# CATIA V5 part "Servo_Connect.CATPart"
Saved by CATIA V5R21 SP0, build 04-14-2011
Part number: Servo_Connect
Bounding box of the stored display mesh (mm): x 0 to 5, y -12.25 to 12.25, z -12.161 to 12.161
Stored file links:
  F:\教程\Robotic_Arm_Arduino_Kinect\机械臂CAD\Arm_Detailed_Design\Servo_Connect.CATPart
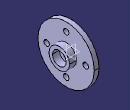
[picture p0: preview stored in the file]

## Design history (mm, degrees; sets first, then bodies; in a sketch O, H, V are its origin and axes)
Body1 (main body)
  Sketch1 on yz-plane, origin (0, 0, 0), H (0, 1, 0), V (0, 0, 1)
    circle A1 centre (0, 0) radius 12.25
    circle A2 centre (0, 8.5) radius 1.25
    point P1 (0, 8.5)
    circle A3 centre (8.5, 0) radius 1.25
    point P2 (8.5, 0)
    circle A4 centre (0, -8.5) radius 1.25
    point P3 (0, -8.5)
    circle A5 centre (-8.5, 0) radius 1.25
    point P4 (-8.5, 0)
    radius A1 = 12.25
    radius A2 = 1.25
    radius A3 = 1.25
    radius A4 = 1.25
    radius A5 = 1.25
    distance H P1 = 8.5
    distance P2 V = 8.5
    distance P3 H = 8.5
    distance P4 V = 8.5
    coincidence: P1 V, P2 H, P3 V, P4 H
  Pad1: profile Sketch1, direction (1, 0, 0), length 2
  Sketch2 on end face of Pad1, origin (2, 0, 0), H (0, 1, 0), V (0, 0, 1)
    circle A1 centre (0, 0) radius 3
    circle A2 centre (0, 0) radius 4.5
    radius A1 = 3
    radius A2 = 4.5
  Pad2: profile Sketch2, direction (1, 0, 0), length 3
  Sketch3 on start face of Pad1, origin (0, 0, 0), H (0, -1, 0), V (0, 0, 1)
    circle A1 centre (0, 0) radius 1.5
    radius A1 = 1.5
  Pocket1: profile Sketch3, direction (1, 0, 0), through (limit type 3)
